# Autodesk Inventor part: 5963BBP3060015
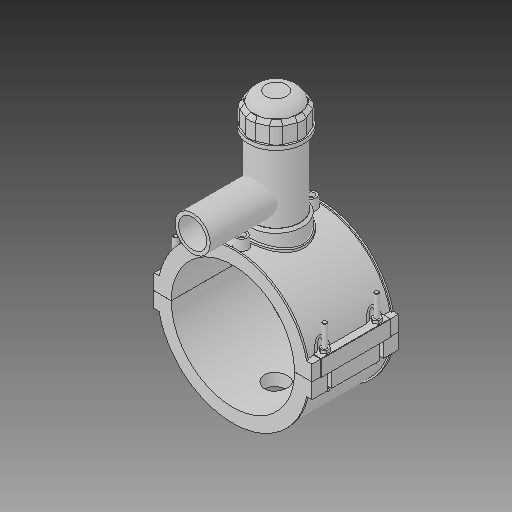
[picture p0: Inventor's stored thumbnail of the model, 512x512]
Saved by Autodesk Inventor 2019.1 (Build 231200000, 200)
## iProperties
Created: 2017-07
Part Number: 5963BBP3060015
Material: Generic
Description: PLASSON TAPPING SADDLE 6''IPS x 1 1/2''IPS
Document SubType Name: Modeling
Designer: KIM
Density: 1 g/cm^3
Appearance: Default
Author: KIM
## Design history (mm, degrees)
derived "5963BBP_5963BUP.ipt"
feature "Solid1::5963BBP_5963BUP.ipt"
feature "Solid2::5963BBP_5963BUP.ipt"
feature "Solid3::5963BBP_5963BUP.ipt"
tag "TaggingFeature1"
body "Solid1"
body "Solid2"
body "Solid3"
other parameters: "d0" = 168, "d2" = 215.9, "d3" = 42, "d4" = 118.11, "d5" = 0, "d6" = 0.1, "d8" = 0, "d19" = 6, "d20" = 6, "d21" = 70.866, "d23" = 0, "d24" = 35.433, "d26" = 0, "d27" = 3, "d28" = 3, "d29" = 3, "d30" = 56, "d31" = 6, "d32" = 0, "d33" = 0, "d34" = 0.6, "d40" = 104.832, "d41" = 75.6, "d43" = 0, "d45" = 0, "d47" = 171.666, "d70" = 15, "d72" = 0, "d73" = 6, "d75" = 5, "d76" = 0, "d77" = 8.4, "d78" = 114, "d79" = 15, "d80" = 47.244, "d82" = 5 deg, "d84" = 4, "d85" = 14, "d86" = 0, "d87" = 3, "d88" = 0, "d89" = 1, "d90" = 1, "d91" = 94.488, "d92" = 0, "d93" = 0.5, "d94" = 88.42105, "d96" = 205.632, "d97" = 2.3622, "d98" = 0, "d102" = 1.68, "d120" = 140 deg, "d121" = 24.228, "d122" = 20 deg, "d123" = 403.2, "d124" = 120.96, "d126" = 0, "d143" = 173.04, "d145" = 25.84615, "d149" = 2.52, "d150" = 28.43077, "d153" = 118.11, "d154" = 0, "d156" = 100.8, "d157" = 160 deg, "d159" = 6.72, "d161" = 2.52, "d162" = 70.866, "d163" = 0, "d164" = 84, "d167" = 16.8, "d168" = 98.34146, "d170" = 3.2805, "d172" = 0, "d173" = 1, "d175" = 84, "d176" = 20 deg, "d177" = 11.76, "d178" = 33.6, "d180" = 0, "d183" = 13.44, "d184" = 9.408, "d185" = 38.38575, "d186" = 38.38575, "d187" = 100.8, "d188" = 10.08, "d189" = 11.76, "d190" = 0, "d191" = 151.2, "d193" = 6.9984, "d194" = 4.13385, "d195" = 90 deg, "d197" = 0, "d199" = 0, "d200" = 16.8, "d202" = 0, "d203" = 177.038, "d204" = 71.82, "d205" = 52.92, "d206" = 64.26, "d207" = 132.7785, "d208" = 138.08964, "d209" = 164.64534, "d210" = 65.016, "d211" = 75.6, "d212" = 60.48, "d213" = 36.8766, "d216" = 0, "d217" = 16.8, "d218" = 16.8, "d219" = 3.36, "d222" = 168, "d224" = 0, "d225" = 65.024, "d226" = 48.1, "d227" = 38.48, "d228" = 114.046, "d230" = 5.04, "d_" = 168, "B_" = 215.9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
